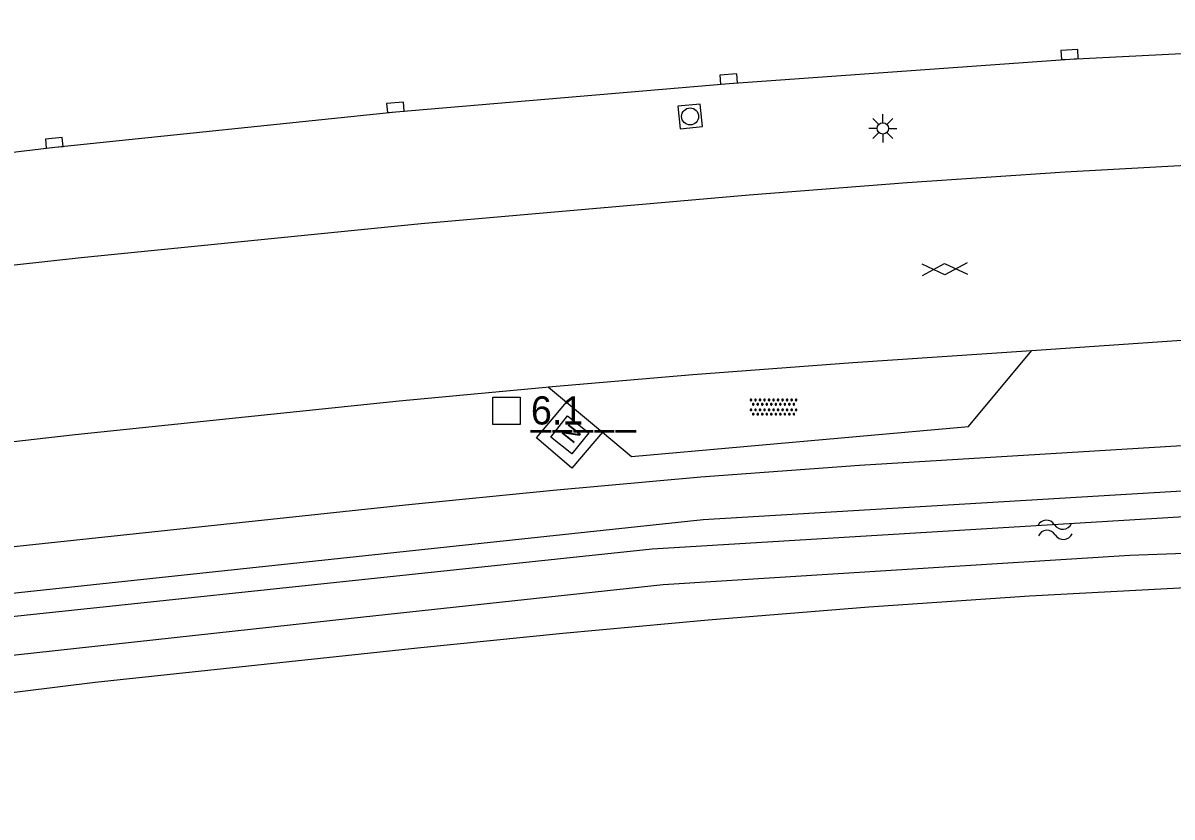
# Model space of a CAD drawing. Extents: x 133000 to 136000, y 400500 to 403500.
# Drawn here: x 134012.4 to 134063.3, y 401141.7 to 401176.9 of the extents above; entities that cross this region are included whole.
import ezdxf

# ---------------------------------------------------------------- set-up
doc = ezdxf.new("R2010")
doc.units = 0
for name, color, linetype in [('gg-afsc-faunaraster', 7, 'Continuous'), ('gg-knt-verharding', 7, 'Continuous'), ('gg-kntw-bovenkant insteek waterloop', 7, 'Continuous'), ('gg-kntw-waterlijn', 7, 'Continuous'), ('gt-anno-nummer hm paal', 7, 'Continuous'), ('gt-symb-gesloten verharding', 7, 'Continuous'), ('gt-symb-hm paal', 7, 'Continuous'), ('gt-symb-kolk', 7, 'Continuous'), ('gt-symb-lichtmast', 7, 'Continuous'), ('gt-symb-nortonput', 7, 'Continuous'), ('gt-symb-overige verharding', 7, 'Continuous'), ('gt-symb-rioolschacht', 7, 'Continuous'), ('gt-symb-watersymbool', 7, 'Continuous')]:
    doc.layers.add(name, color=color, linetype=linetype)

# ---------------------------------------------------------------- blocks, each defined once
blk = doc.blocks.new('gt0-GESVH1')
at = {"layer": 'gt-symb-gesloten verharding'}
for p, q in [((-0.992, -0.261), (0.008, 0.239)), ((0.008, -0.261), (-0.992, 0.239)), ((0.008, 0.239), (1.008, -0.261)), ((1.008, 0.239), (0.008, -0.261))]:
    blk.add_line(p, q, dxfattribs=at)
blk = doc.blocks.new('gt0-LMAST')
at = {"layer": 'gt-symb-lichtmast'}
for p, q in [((-0.005, 0.246), (-0.005, 0.621)), ((-0.182, 0.173), (-0.447, 0.438)), ((0.172, 0.173), (0.437, 0.438)), ((-0.255, -0.004), (-0.63, -0.004)), ((-0.182, -0.181), (-0.447, -0.446)), ((-0.005, -0.254), (-0.005, -0.629)), ((0.437, -0.446), (0.172, -0.181)), ((0.245, -0.004), (0.62, -0.004))]:
    blk.add_line(p, q, dxfattribs=at)
blk.add_circle((-0.005, -0.004), 0.25, dxfattribs=at)
blk = doc.blocks.new('gt0-RS')
at = {"layer": 'gt-symb-rioolschacht'}
blk.add_lwpolyline([(-0.5, -0.5), (0.5, -0.5), (0.5, 0.5), (-0.5, 0.5)], close=True, dxfattribs=at)
blk.add_circle((0, 0), 0.375, dxfattribs=at)
blk = doc.blocks.new('gt0-KOLK')
at = {"layer": 'gt-symb-kolk'}
blk.add_lwpolyline([(0, 0), (0.375, 0), (0.375, 0.4), (-0.375, 0.4), (-0.375, 0), (0, 0)], dxfattribs=at)
blk = doc.blocks.new('gt0-WA')
at = {"layer": 'gt-symb-watersymbool'}
for centre, start, end in [((-0.323, 0.022), 28.0725, 151.9275), ((0.427, 0.422), 208.0725, 331.9275), ((-0.323, -0.428), 28.0725, 151.9275), ((0.427, -0.028), 208.0725, 331.9275)]:
    blk.add_arc(centre, 0.425, start, end, dxfattribs=at)
blk = doc.blocks.new('gt0-OVH')
at = {"layer": 'gt-symb-overige verharding'}
for points in [[(-0.972, 0.298), (-0.967, 0.308), (-0.965, 0.319), (-0.966, 0.33), (-0.971, 0.34), (-0.978, 0.348), (-0.988, 0.353), (-0.999, 0.355), (-1.01, 0.354), (-1.02, 0.349), (-1.028, 0.342), (-1.033, 0.332), (-1.035, 0.321), (-1.034, 0.31), (-1.029, 0.3), (-1.022, 0.292), (-1.012, 0.287), (-1.001, 0.285), (-0.99, 0.286), (-0.98, 0.291)], [(-0.872, 0.106), (-0.867, 0.116), (-0.865, 0.126), (-0.866, 0.137), (-0.871, 0.147), (-0.878, 0.156), (-0.888, 0.161), (-0.899, 0.163), (-0.91, 0.162), (-0.92, 0.157), (-0.928, 0.15), (-0.933, 0.14), (-0.935, 0.129), (-0.934, 0.118), (-0.929, 0.108), (-0.922, 0.1), (-0.912, 0.095), (-0.901, 0.092), (-0.89, 0.094), (-0.88, 0.098)], [(-0.772, 0.298), (-0.767, 0.308), (-0.765, 0.319), (-0.766, 0.33), (-0.771, 0.34), (-0.778, 0.348), (-0.788, 0.353), (-0.799, 0.355), (-0.81, 0.354), (-0.82, 0.349), (-0.828, 0.342), (-0.833, 0.332), (-0.835, 0.321), (-0.834, 0.31), (-0.829, 0.3), (-0.822, 0.292), (-0.812, 0.287), (-0.801, 0.285), (-0.79, 0.286), (-0.78, 0.291)], [(-0.672, 0.106), (-0.667, 0.116), (-0.665, 0.126), (-0.666, 0.137), (-0.671, 0.147), (-0.678, 0.156), (-0.688, 0.161), (-0.699, 0.163), (-0.71, 0.162), (-0.72, 0.157), (-0.728, 0.15), (-0.733, 0.14), (-0.735, 0.129), (-0.734, 0.118), (-0.729, 0.108), (-0.722, 0.1), (-0.712, 0.095), (-0.701, 0.092), (-0.69, 0.094), (-0.68, 0.098)], [(-0.572, 0.298), (-0.567, 0.308), (-0.565, 0.319), (-0.566, 0.33), (-0.571, 0.34), (-0.578, 0.348), (-0.588, 0.353), (-0.599, 0.355), (-0.61, 0.354), (-0.62, 0.349), (-0.628, 0.342), (-0.633, 0.332), (-0.635, 0.321), (-0.634, 0.31), (-0.629, 0.3), (-0.622, 0.292), (-0.612, 0.287), (-0.601, 0.285), (-0.59, 0.286), (-0.58, 0.291)], [(-0.472, 0.106), (-0.467, 0.116), (-0.465, 0.126), (-0.466, 0.137), (-0.471, 0.147), (-0.478, 0.156), (-0.488, 0.161), (-0.499, 0.163), (-0.51, 0.162), (-0.52, 0.157), (-0.528, 0.15), (-0.533, 0.14), (-0.535, 0.129), (-0.534, 0.118), (-0.529, 0.108), (-0.522, 0.1), (-0.512, 0.095), (-0.501, 0.092), (-0.49, 0.094), (-0.48, 0.098)], [(-0.372, 0.298), (-0.367, 0.308), (-0.365, 0.319), (-0.366, 0.33), (-0.371, 0.34), (-0.378, 0.348), (-0.388, 0.353), (-0.399, 0.355), (-0.41, 0.354), (-0.42, 0.349), (-0.428, 0.342), (-0.433, 0.332), (-0.435, 0.321), (-0.434, 0.31), (-0.429, 0.3), (-0.422, 0.292), (-0.412, 0.287), (-0.401, 0.285), (-0.39, 0.286), (-0.38, 0.291)], [(-0.272, 0.106), (-0.267, 0.116), (-0.265, 0.126), (-0.266, 0.137), (-0.271, 0.147), (-0.278, 0.156), (-0.288, 0.161), (-0.299, 0.163), (-0.31, 0.162), (-0.32, 0.157), (-0.328, 0.15), (-0.333, 0.14), (-0.335, 0.129), (-0.334, 0.118), (-0.329, 0.108), (-0.322, 0.1), (-0.312, 0.095), (-0.301, 0.092), (-0.29, 0.094), (-0.28, 0.098)], [(-0.172, 0.298), (-0.167, 0.308), (-0.165, 0.319), (-0.166, 0.33), (-0.171, 0.34), (-0.178, 0.348), (-0.188, 0.353), (-0.199, 0.355), (-0.21, 0.354), (-0.22, 0.349), (-0.228, 0.342), (-0.233, 0.332), (-0.235, 0.321), (-0.234, 0.31), (-0.229, 0.3), (-0.222, 0.292), (-0.212, 0.287), (-0.201, 0.285), (-0.19, 0.286), (-0.18, 0.291)], [(-0.072, 0.106), (-0.067, 0.116), (-0.065, 0.126), (-0.066, 0.137), (-0.071, 0.147), (-0.078, 0.156), (-0.088, 0.161), (-0.099, 0.163), (-0.11, 0.162), (-0.12, 0.157), (-0.128, 0.15), (-0.133, 0.14), (-0.135, 0.129), (-0.134, 0.118), (-0.129, 0.108), (-0.122, 0.1), (-0.112, 0.095), (-0.101, 0.092), (-0.09, 0.094), (-0.08, 0.098)], [(0.028, 0.298), (0.033, 0.308), (0.035, 0.319), (0.034, 0.33), (0.029, 0.34), (0.022, 0.348), (0.012, 0.353), (0.001, 0.355), (-0.01, 0.354), (-0.02, 0.349), (-0.028, 0.342), (-0.033, 0.332), (-0.035, 0.321), (-0.034, 0.31), (-0.029, 0.3), (-0.022, 0.292), (-0.012, 0.287), (-0.001, 0.285), (0.01, 0.286), (0.02, 0.291)], [(0.128, 0.106), (0.133, 0.116), (0.135, 0.126), (0.134, 0.137), (0.129, 0.147), (0.122, 0.156), (0.112, 0.161), (0.101, 0.163), (0.09, 0.162), (0.08, 0.157), (0.072, 0.15), (0.067, 0.14), (0.065, 0.129), (0.066, 0.118), (0.071, 0.108), (0.078, 0.1), (0.088, 0.095), (0.099, 0.092), (0.11, 0.094), (0.12, 0.098)], [(0.228, 0.298), (0.233, 0.308), (0.235, 0.319), (0.234, 0.33), (0.229, 0.34), (0.222, 0.348), (0.212, 0.353), (0.201, 0.355), (0.19, 0.354), (0.18, 0.349), (0.172, 0.342), (0.167, 0.332), (0.165, 0.321), (0.166, 0.31), (0.171, 0.3), (0.178, 0.292), (0.188, 0.287), (0.199, 0.285), (0.21, 0.286), (0.22, 0.291)], [(0.328, 0.106), (0.333, 0.116), (0.335, 0.126), (0.334, 0.137), (0.329, 0.147), (0.322, 0.156), (0.312, 0.161), (0.301, 0.163), (0.29, 0.162), (0.28, 0.157), (0.272, 0.15), (0.267, 0.14), (0.265, 0.129), (0.266, 0.118), (0.271, 0.108), (0.278, 0.1), (0.288, 0.095), (0.299, 0.092), (0.31, 0.094), (0.32, 0.098)], [(0.428, 0.298), (0.433, 0.308), (0.435, 0.319), (0.434, 0.33), (0.429, 0.34), (0.422, 0.348), (0.412, 0.353), (0.401, 0.355), (0.39, 0.354), (0.38, 0.349), (0.372, 0.342), (0.367, 0.332), (0.365, 0.321), (0.366, 0.31), (0.371, 0.3), (0.378, 0.292), (0.388, 0.287), (0.399, 0.285), (0.41, 0.286), (0.42, 0.291)], [(0.528, 0.106), (0.533, 0.116), (0.535, 0.126), (0.534, 0.137), (0.529, 0.147), (0.522, 0.156), (0.512, 0.161), (0.501, 0.163), (0.49, 0.162), (0.48, 0.157), (0.472, 0.15), (0.467, 0.14), (0.465, 0.129), (0.466, 0.118), (0.471, 0.108), (0.478, 0.1), (0.488, 0.095), (0.499, 0.092), (0.51, 0.094), (0.52, 0.098)], [(0.628, 0.298), (0.633, 0.308), (0.635, 0.319), (0.634, 0.33), (0.629, 0.34), (0.622, 0.348), (0.612, 0.353), (0.601, 0.355), (0.59, 0.354), (0.58, 0.349), (0.572, 0.342), (0.567, 0.332), (0.565, 0.321), (0.566, 0.31), (0.571, 0.3), (0.578, 0.292), (0.588, 0.287), (0.599, 0.285), (0.61, 0.286), (0.62, 0.291)], [(0.728, 0.106), (0.733, 0.116), (0.735, 0.126), (0.734, 0.137), (0.729, 0.147), (0.722, 0.156), (0.712, 0.161), (0.701, 0.163), (0.69, 0.162), (0.68, 0.157), (0.672, 0.15), (0.667, 0.14), (0.665, 0.129), (0.666, 0.118), (0.671, 0.108), (0.678, 0.1), (0.688, 0.095), (0.699, 0.092), (0.71, 0.094), (0.72, 0.098)], [(0.828, 0.298), (0.833, 0.308), (0.835, 0.319), (0.834, 0.33), (0.829, 0.34), (0.822, 0.348), (0.812, 0.353), (0.801, 0.355), (0.79, 0.354), (0.78, 0.349), (0.772, 0.342), (0.767, 0.332), (0.765, 0.321), (0.766, 0.31), (0.771, 0.3), (0.778, 0.292), (0.788, 0.287), (0.799, 0.285), (0.81, 0.286), (0.82, 0.291)], [(0.928, 0.106), (0.933, 0.116), (0.935, 0.126), (0.934, 0.137), (0.929, 0.147), (0.922, 0.156), (0.912, 0.161), (0.901, 0.163), (0.89, 0.162), (0.88, 0.157), (0.872, 0.15), (0.867, 0.14), (0.865, 0.129), (0.866, 0.118), (0.871, 0.108), (0.878, 0.1), (0.888, 0.095), (0.899, 0.092), (0.91, 0.094), (0.92, 0.098)], [(1.028, 0.298), (1.033, 0.308), (1.035, 0.319), (1.034, 0.33), (1.029, 0.34), (1.022, 0.348), (1.012, 0.353), (1.001, 0.355), (0.99, 0.354), (0.98, 0.349), (0.972, 0.342), (0.967, 0.332), (0.965, 0.321), (0.966, 0.31), (0.971, 0.3), (0.978, 0.292), (0.988, 0.287), (0.999, 0.285), (1.01, 0.286), (1.02, 0.291)], [(-0.972, -0.142), (-0.967, -0.132), (-0.965, -0.121), (-0.966, -0.11), (-0.971, -0.1), (-0.978, -0.092), (-0.988, -0.087), (-0.999, -0.085), (-1.01, -0.086), (-1.02, -0.091), (-1.028, -0.098), (-1.033, -0.108), (-1.035, -0.119), (-1.034, -0.13), (-1.029, -0.14), (-1.022, -0.148), (-1.012, -0.153), (-1.001, -0.155), (-0.99, -0.154), (-0.98, -0.149)], [(-0.872, -0.334), (-0.867, -0.324), (-0.865, -0.314), (-0.866, -0.303), (-0.871, -0.293), (-0.878, -0.284), (-0.888, -0.279), (-0.899, -0.277), (-0.91, -0.278), (-0.92, -0.283), (-0.928, -0.29), (-0.933, -0.3), (-0.935, -0.311), (-0.934, -0.322), (-0.929, -0.332), (-0.922, -0.34), (-0.912, -0.345), (-0.901, -0.348), (-0.89, -0.346), (-0.88, -0.342)], [(-0.772, -0.142), (-0.767, -0.132), (-0.765, -0.121), (-0.766, -0.11), (-0.771, -0.1), (-0.778, -0.092), (-0.788, -0.087), (-0.799, -0.085), (-0.81, -0.086), (-0.82, -0.091), (-0.828, -0.098), (-0.833, -0.108), (-0.835, -0.119), (-0.834, -0.13), (-0.829, -0.14), (-0.822, -0.148), (-0.812, -0.153), (-0.801, -0.155), (-0.79, -0.154), (-0.78, -0.149)], [(-0.672, -0.334), (-0.667, -0.324), (-0.665, -0.314), (-0.666, -0.303), (-0.671, -0.293), (-0.678, -0.284), (-0.688, -0.279), (-0.699, -0.277), (-0.71, -0.278), (-0.72, -0.283), (-0.728, -0.29), (-0.733, -0.3), (-0.735, -0.311), (-0.734, -0.322), (-0.729, -0.332), (-0.722, -0.34), (-0.712, -0.345), (-0.701, -0.348), (-0.69, -0.346), (-0.68, -0.342)], [(-0.572, -0.142), (-0.567, -0.132), (-0.565, -0.121), (-0.566, -0.11), (-0.571, -0.1), (-0.578, -0.092), (-0.588, -0.087), (-0.599, -0.085), (-0.61, -0.086), (-0.62, -0.091), (-0.628, -0.098), (-0.633, -0.108), (-0.635, -0.119), (-0.634, -0.13), (-0.629, -0.14), (-0.622, -0.148), (-0.612, -0.153), (-0.601, -0.155), (-0.59, -0.154), (-0.58, -0.149)], [(-0.472, -0.334), (-0.467, -0.324), (-0.465, -0.314), (-0.466, -0.303), (-0.471, -0.293), (-0.478, -0.284), (-0.488, -0.279), (-0.499, -0.277), (-0.51, -0.278), (-0.52, -0.283), (-0.528, -0.29), (-0.533, -0.3), (-0.535, -0.311), (-0.534, -0.322), (-0.529, -0.332), (-0.522, -0.34), (-0.512, -0.345), (-0.501, -0.348), (-0.49, -0.346), (-0.48, -0.342)], [(-0.372, -0.142), (-0.367, -0.132), (-0.365, -0.121), (-0.366, -0.11), (-0.371, -0.1), (-0.378, -0.092), (-0.388, -0.087), (-0.399, -0.085), (-0.41, -0.086), (-0.42, -0.091), (-0.428, -0.098), (-0.433, -0.108), (-0.435, -0.119), (-0.434, -0.13), (-0.429, -0.14), (-0.422, -0.148), (-0.412, -0.153), (-0.401, -0.155), (-0.39, -0.154), (-0.38, -0.149)], [(-0.272, -0.334), (-0.267, -0.324), (-0.265, -0.314), (-0.266, -0.303), (-0.271, -0.293), (-0.278, -0.284), (-0.288, -0.279), (-0.299, -0.277), (-0.31, -0.278), (-0.32, -0.283), (-0.328, -0.29), (-0.333, -0.3), (-0.335, -0.311), (-0.334, -0.322), (-0.329, -0.332), (-0.322, -0.34), (-0.312, -0.345), (-0.301, -0.348), (-0.29, -0.346), (-0.28, -0.342)], [(-0.172, -0.142), (-0.167, -0.132), (-0.165, -0.121), (-0.166, -0.11), (-0.171, -0.1), (-0.178, -0.092), (-0.188, -0.087), (-0.199, -0.085), (-0.21, -0.086), (-0.22, -0.091), (-0.228, -0.098), (-0.233, -0.108), (-0.235, -0.119), (-0.234, -0.13), (-0.229, -0.14), (-0.222, -0.148), (-0.212, -0.153), (-0.201, -0.155), (-0.19, -0.154), (-0.18, -0.149)], [(-0.072, -0.334), (-0.067, -0.324), (-0.065, -0.314), (-0.066, -0.303), (-0.071, -0.293), (-0.078, -0.284), (-0.088, -0.279), (-0.099, -0.277), (-0.11, -0.278), (-0.12, -0.283), (-0.128, -0.29), (-0.133, -0.3), (-0.135, -0.311), (-0.134, -0.322), (-0.129, -0.332), (-0.122, -0.34), (-0.112, -0.345), (-0.101, -0.348), (-0.09, -0.346), (-0.08, -0.342)], [(0.028, -0.142), (0.033, -0.132), (0.035, -0.121), (0.034, -0.11), (0.029, -0.1), (0.022, -0.092), (0.012, -0.087), (0.001, -0.085), (-0.01, -0.086), (-0.02, -0.091), (-0.028, -0.098), (-0.033, -0.108), (-0.035, -0.119), (-0.034, -0.13), (-0.029, -0.14), (-0.022, -0.148), (-0.012, -0.153), (-0.001, -0.155), (0.01, -0.154), (0.02, -0.149)], [(0.128, -0.334), (0.133, -0.324), (0.135, -0.314), (0.134, -0.303), (0.129, -0.293), (0.122, -0.284), (0.112, -0.279), (0.101, -0.277), (0.09, -0.278), (0.08, -0.283), (0.072, -0.29), (0.067, -0.3), (0.065, -0.311), (0.066, -0.322), (0.071, -0.332), (0.078, -0.34), (0.088, -0.345), (0.099, -0.348), (0.11, -0.346), (0.12, -0.342)], [(0.228, -0.142), (0.233, -0.132), (0.235, -0.121), (0.234, -0.11), (0.229, -0.1), (0.222, -0.092), (0.212, -0.087), (0.201, -0.085), (0.19, -0.086), (0.18, -0.091), (0.172, -0.098), (0.167, -0.108), (0.165, -0.119), (0.166, -0.13), (0.171, -0.14), (0.178, -0.148), (0.188, -0.153), (0.199, -0.155), (0.21, -0.154), (0.22, -0.149)], [(0.328, -0.334), (0.333, -0.324), (0.335, -0.314), (0.334, -0.303), (0.329, -0.293), (0.322, -0.284), (0.312, -0.279), (0.301, -0.277), (0.29, -0.278), (0.28, -0.283), (0.272, -0.29), (0.267, -0.3), (0.265, -0.311), (0.266, -0.322), (0.271, -0.332), (0.278, -0.34), (0.288, -0.345), (0.299, -0.348), (0.31, -0.346), (0.32, -0.342)], [(0.428, -0.142), (0.433, -0.132), (0.435, -0.121), (0.434, -0.11), (0.429, -0.1), (0.422, -0.092), (0.412, -0.087), (0.401, -0.085), (0.39, -0.086), (0.38, -0.091), (0.372, -0.098), (0.367, -0.108), (0.365, -0.119), (0.366, -0.13), (0.371, -0.14), (0.378, -0.148), (0.388, -0.153), (0.399, -0.155), (0.41, -0.154), (0.42, -0.149)], [(0.528, -0.334), (0.533, -0.324), (0.535, -0.314), (0.534, -0.303), (0.529, -0.293), (0.522, -0.284), (0.512, -0.279), (0.501, -0.277), (0.49, -0.278), (0.48, -0.283), (0.472, -0.29), (0.467, -0.3), (0.465, -0.311), (0.466, -0.322), (0.471, -0.332), (0.478, -0.34), (0.488, -0.345), (0.499, -0.348), (0.51, -0.346), (0.52, -0.342)], [(0.628, -0.142), (0.633, -0.132), (0.635, -0.121), (0.634, -0.11), (0.629, -0.1), (0.622, -0.092), (0.612, -0.087), (0.601, -0.085), (0.59, -0.086), (0.58, -0.091), (0.572, -0.098), (0.567, -0.108), (0.565, -0.119), (0.566, -0.13), (0.571, -0.14), (0.578, -0.148), (0.588, -0.153), (0.599, -0.155), (0.61, -0.154), (0.62, -0.149)], [(0.728, -0.334), (0.733, -0.324), (0.735, -0.314), (0.734, -0.303), (0.729, -0.293), (0.722, -0.284), (0.712, -0.279), (0.701, -0.277), (0.69, -0.278), (0.68, -0.283), (0.672, -0.29), (0.667, -0.3), (0.665, -0.311), (0.666, -0.322), (0.671, -0.332), (0.678, -0.34), (0.688, -0.345), (0.699, -0.348), (0.71, -0.346), (0.72, -0.342)], [(0.828, -0.142), (0.833, -0.132), (0.835, -0.121), (0.834, -0.11), (0.829, -0.1), (0.822, -0.092), (0.812, -0.087), (0.801, -0.085), (0.79, -0.086), (0.78, -0.091), (0.772, -0.098), (0.767, -0.108), (0.765, -0.119), (0.766, -0.13), (0.771, -0.14), (0.778, -0.148), (0.788, -0.153), (0.799, -0.155), (0.81, -0.154), (0.82, -0.149)], [(0.928, -0.334), (0.933, -0.324), (0.935, -0.314), (0.934, -0.303), (0.929, -0.293), (0.922, -0.284), (0.912, -0.279), (0.901, -0.277), (0.89, -0.278), (0.88, -0.283), (0.872, -0.29), (0.867, -0.3), (0.865, -0.311), (0.866, -0.322), (0.871, -0.332), (0.878, -0.34), (0.888, -0.345), (0.899, -0.348), (0.91, -0.346), (0.92, -0.342)], [(1.028, -0.142), (1.033, -0.132), (1.035, -0.121), (1.034, -0.11), (1.029, -0.1), (1.022, -0.092), (1.012, -0.087), (1.001, -0.085), (0.99, -0.086), (0.98, -0.091), (0.972, -0.098), (0.967, -0.108), (0.965, -0.119), (0.966, -0.13), (0.971, -0.14), (0.978, -0.148), (0.988, -0.153), (0.999, -0.155), (1.01, -0.154), (1.02, -0.149)]]:
    blk.add_lwpolyline(points, close=True, dxfattribs=at)
blk = doc.blocks.new('gt0-HMpaal')
at = {"layer": 'gt-symb-hm paal'}
blk.add_lwpolyline([(-0.6, 0.6), (0.6, 0.6), (0.6, -0.6), (-0.6, -0.6)], close=True, dxfattribs=at)
blk = doc.blocks.new('gt0-NPUT')
at = {"layer": 'gt-symb-nortonput'}
blk.add_lwpolyline([(-0.566, -0.608), (-0.566, 0.592), (0.634, 0.592), (0.634, -0.608)], close=True, dxfattribs=at)
blk.add_text('N', height=0.7, dxfattribs=at).set_placement((-0.221, -0.381))

msp = doc.modelspace()

# ---------------------------------------------------------------- linework, layer by layer
at = {"layer": 'gg-afsc-faunaraster'}
msp.add_lwpolyline([(134001.403, 401145.885), (134009.009, 401146.892), (134015.57, 401147.707), (134029.863, 401149.232), (134036.298, 401149.88), (134042.738, 401150.474), (134049.859, 401151.044), (134056.987, 401151.531), (134064.195, 401151.921), (134071.407, 401152.234), (134084.815, 401152.64), (134092.405, 401152.939)], dxfattribs=at)
at = {"layer": 'gg-knt-verharding'}
for p, q in [((134035.667, 401160.771), (134036.457, 401160.112)), ((134036.457, 401160.112), (134038.055, 401158.779))]:
    msp.add_line(p, q, dxfattribs=at)
for points in [[(133863.668, 401141.731), (133878.686, 401145.85), (133893.656, 401149.793), (133908.679, 401153.423), (133923.633, 401156.734), (133938.691, 401159.841), (133949.02, 401161.877), (133953.643, 401162.725), (133968.728, 401165.088), (133985.473, 401167.838), (133998.781, 401169.625), (134013.783, 401171.406), (134028.899, 401172.974), (134043.668, 401174.228), (134058.769, 401175.314), (134073.66, 401176.068), (134088.719, 401176.606), (134103.723, 401176.891), (134119.804, 401176.912), (134137.108, 401176.608)], [(134163.847, 401170.733), (134140.343, 401171.64), (134121.219, 401171.924), (134113.971, 401171.972), (134106.723, 401171.956), (134098.137, 401171.828), (134089.553, 401171.626), (134081.828, 401171.387), (134074.105, 401171.086), (134066.33, 401170.727), (134058.558, 401170.298), (134051.554, 401169.823), (134044.555, 401169.281), (134030.021, 401168.013), (134014.957, 401166.508), (134007.559, 401165.701), (134000, 401164.711)], [(134194.473, 401161.298), (134184.944, 401161.972), (134171.446, 401162.717), (134136.905, 401163.989), (134122.944, 401164.181), (134112.701, 401164.198), (134098.857, 401164.124), (134091.892, 401164.011), (134084.928, 401163.833), (134077.856, 401163.569), (134070.787, 401163.234), (134063.512, 401162.822), (134057.065, 401162.39)], [(134057.065, 401162.39), (134049.151, 401161.86), (134042.065, 401161.316), (134035.667, 401160.771)], [(134038.055, 401158.779), (134039.351, 401157.699), (134054.28, 401159.036), (134057.065, 401162.39)], [(134035.667, 401160.771), (134035.553, 401160.761), (134029.046, 401160.155), (134014.696, 401158.666), (134007.801, 401157.888), (134000, 401156.869)], [(134038.055, 401158.779), (134036.705, 401157.192), (134035.13, 401158.538), (134036.457, 401160.112)]]:
    msp.add_lwpolyline(points, dxfattribs=at)
at = {"layer": 'gg-kntw-bovenkant insteek waterloop'}
for points in [[(134129.129, 401158.815), (134127.635, 401159.02), (134127.374, 401159.168), (134127.37, 401159.709), (134124.565, 401159.592), (134112.364, 401159.684), (134105.657, 401159.704), (134098.95, 401159.671), (134091.935, 401159.548), (134084.922, 401159.336), (134077.959, 401159.006), (134071, 401158.613), (134049.454, 401157.299), (134042.42, 401156.793), (134035.869, 401156.203), (134029.325, 401155.547), (134008.635, 401153.343), (134003.487, 401152.722), (134000, 401152.258), (133986.172, 401150.35)], [(134005.95, 401148.252), (134026.928, 401150.534), (134040.752, 401152.038), (134061.433, 401153.332), (134087.827, 401154.296), (134107.763, 401154.435), (134116.39, 401154.435)]]:
    msp.add_lwpolyline(points, dxfattribs=at)
at = {"layer": 'gg-kntw-waterlijn'}
for points in [[(133970.812, 401145.235), (133971.254, 401145.691), (133979.911, 401147.292), (133987.916, 401148.507), (134000.94, 401150.483), (134019.1, 401152.416), (134042.524, 401154.909), (134078.298, 401157.061), (134126.507, 401157.672)], [(133970.812, 401145.235), (133971.4, 401144.815), (133979.856, 401146.455), (134001.647, 401149.543), (134040.265, 401153.609), (134071.621, 401155.513), (134107.966, 401156.247), (134126.409, 401156.619)]]:
    msp.add_lwpolyline(points, dxfattribs=at)

# ---------------------------------------------------------------- block references
at = {"layer": 'gt-symb-gesloten verharding', "rotation": 1.5466102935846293}
msp.add_blockref('gt0-GESVH1', (134053.22, 401166.013), dxfattribs=at)
at = {"layer": 'gt-symb-hm paal'}
msp.add_blockref('gt0-HMpaal', (134033.804, 401159.726), dxfattribs=at)
at = {"layer": 'gt-symb-kolk'}
for p, rotation in [((134058.769, 401175.314), 2.922472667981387), ((134043.668, 401174.228), 4.1305386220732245), ((134028.899, 401172.974), 4.877880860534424), ((134013.783, 401171.406), 5.910070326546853)]:
    msp.add_blockref('gt0-KOLK', p, dxfattribs=dict(at, rotation=rotation))
at = {"layer": 'gt-symb-lichtmast'}
msp.add_blockref('gt0-LMAST', (134050.487, 401172.246), dxfattribs=at)
at = {"layer": 'gt-symb-nortonput', "rotation": 51.4565372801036}
msp.add_blockref('gt0-NPUT', (134036.58, 401158.642), dxfattribs=at)
at = {"layer": 'gt-symb-overige verharding'}
msp.add_blockref('gt0-OVH', (134045.639, 401159.891), dxfattribs=at)
at = {"layer": 'gt-symb-rioolschacht', "rotation": 5.853091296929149}
msp.add_blockref('gt0-RS', (134041.941, 401172.774), dxfattribs=at)
at = {"layer": 'gt-symb-watersymbool', "rotation": 3.6120749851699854}
msp.add_blockref('gt0-WA', (134058.056, 401154.457), dxfattribs=at)

# ---------------------------------------------------------------- texts
at = {"layer": 'gt-anno-nummer hm paal'}
msp.add_text('6.1', height=1.25, dxfattribs=at).set_placement((134034.885, 401159.122))
at = {"layer": 'gt-symb-hm paal'}
msp.add_text('_____', height=1.25, dxfattribs=at).set_placement((134034.885, 401159.122))

doc.saveas('drawing.dxf')
